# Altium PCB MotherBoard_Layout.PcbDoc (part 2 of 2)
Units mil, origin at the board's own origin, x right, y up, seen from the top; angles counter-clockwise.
Board outline 5200 x 4470 mil, 4 copper layers (Top Layer, Int1 (GND), Int2 (PWR), Bottom Layer), stack 53.912 mil thick; 91 components, 57 nets, 316 pads, 326 vias.
Unrouted connection lines stored in the file: 3.
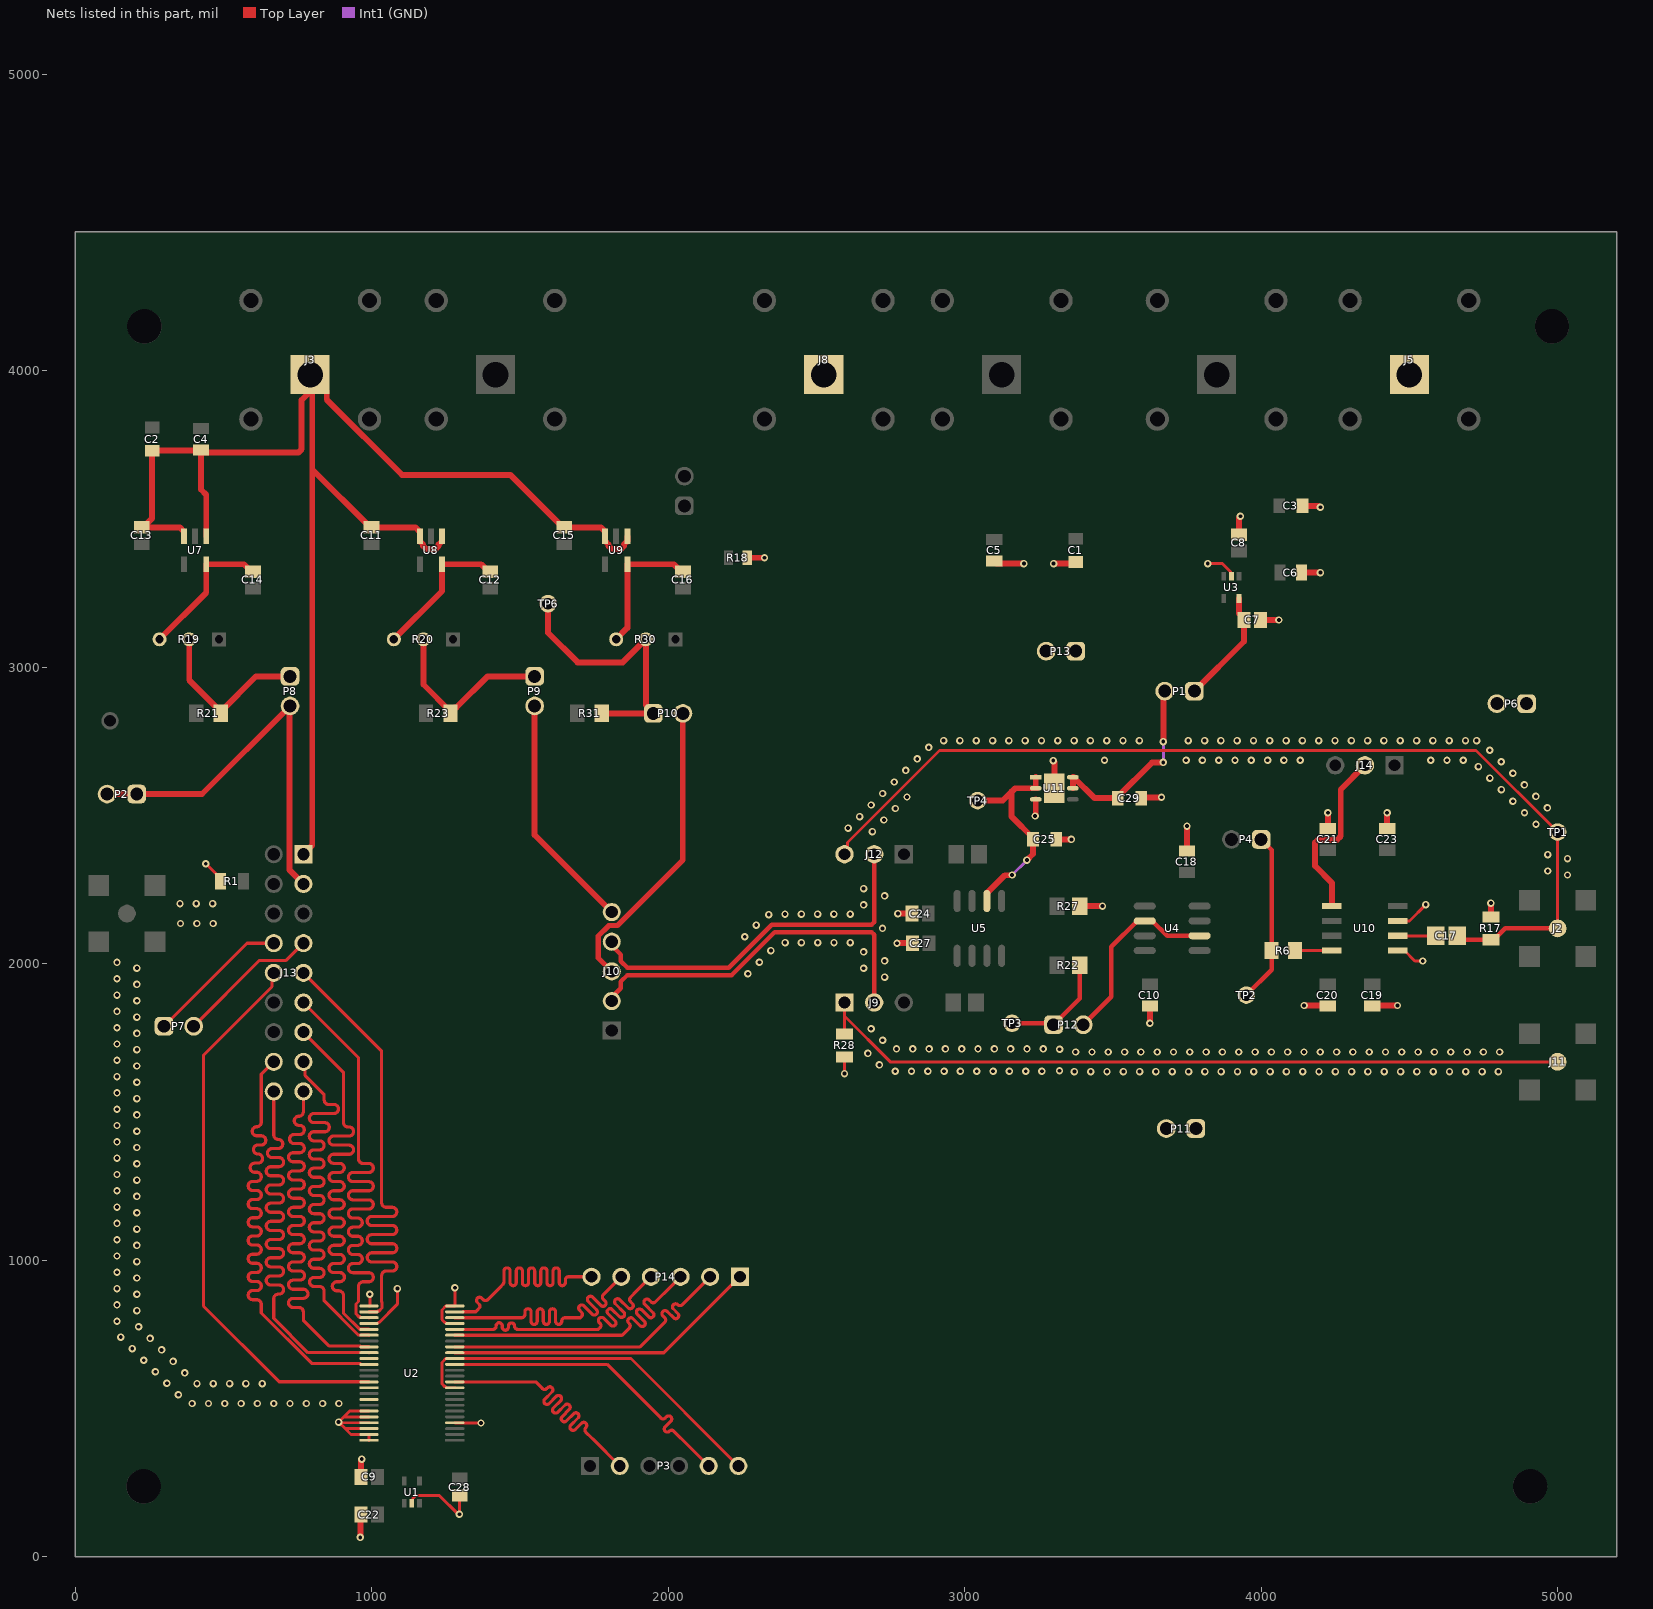
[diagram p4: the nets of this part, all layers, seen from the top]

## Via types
v1: diameter 25, hole 13, Top Layer to Bottom Layer, 326 vias

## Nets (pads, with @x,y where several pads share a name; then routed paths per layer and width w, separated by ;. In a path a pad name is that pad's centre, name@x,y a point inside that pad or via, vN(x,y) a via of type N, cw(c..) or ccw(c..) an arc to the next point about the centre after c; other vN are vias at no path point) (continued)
Code2: J13.16 U2.35 | length 1859.3
  Top Layer w10.7: J13.16@670,1670 628.14,1628.14 628.14,1526 628.14,1466.4 cw(c612.79,1466.4) 612.79,1451.05 ccw(c612.78,1435.7) 597.43,1435.7 ccw(c612.78,1435.7) 612.78,1420.34 628.14,1420.34 cw(c628.14,1404.99) 643.49,1404.99 cw(c628.14,1404.99) 628.14,1389.64 617.05,1389.64 ccw(c617.05,1374.29) 601.7,1374.29 ccw(c617.05,1374.29) 617.05,1358.94 cw(c617.05,1343.59) 632.4,1343.59 cw(c617.05,1343.59) 617.05,1328.24 605.89,1328.24 ccw(c605.89,1312.89) 590.54,1312.89 ccw(c605.89,1312.89) 605.89,1297.54 612.79,1297.53 cw(c612.79,1282.18) 628.14,1282.18 cw(c612.79,1282.18) 612.79,1266.83 599.05,1266.83 ccw(c599.05,1251.48) 583.7,1251.48 ccw(c599.05,1251.48) 599.05,1236.13 612.79,1236.13 cw(c612.79,1220.78) 628.14,1220.78 cw(c612.79,1220.78) 612.79,1205.43 599.05,1205.43 ccw(c599.05,1190.08) 583.7,1190.08 ccw(c599.05,1190.08) 599.05,1174.73 612.79,1174.73 cw(c612.79,1159.37) 628.14,1159.37 cw(c612.79,1159.37) 612.79,1144.02 599.05,1144.02 ccw(c599.05,1128.67) 583.7,1128.67 ccw(c599.05,1128.67) 599.05,1113.32 612.79,1113.32 cw(c612.79,1097.97) 628.14,1097.97 cw(c612.79,1097.97) 612.79,1082.62 599.05,1082.62 ccw(c599.05,1067.27) 583.7,1067.27 ccw(c599.05,1067.27) 599.05,1051.92 612.79,1051.92 cw(c612.79,1036.57) 628.14,1036.57 cw(c612.79,1036.57) 612.79,1021.21 599.05,1021.21 ccw(c599.05,1005.86) 583.7,1005.86 ccw(c599.05,1005.86) 599.05,990.51 612.79,990.51 cw(c612.79,975.16) 628.14,975.16 cw(c612.79,975.16) 612.79,959.81 599.05,959.81 ccw(c599.05,944.46) 583.7,944.46 ccw(c599.05,944.46) 599.05,929.11 612.79,929.11 cw(c612.79,913.76) 628.14,913.76 cw(c612.79,913.76) 612.79,898.41 599.05,898.41 ccw(c599.05,883.05) 583.7,883.05 ccw(c599.05,883.05) 599.05,867.7 612.79,867.7 cw(c612.79,852.35) 628.14,852.35 628.14,847 628.14,822.89 798.14,652.89 961.08,652.89 U2.35@964.06,649.91
Code2_BufferOut: P3.5 U2.14 | length 1067.4
  Top Layer w10.7: U2.14@1280.7,649.53 1794.47,649.53 1971.5,472.5 1975.28,468.72 ccw(c1982.85,476.28) 1990.42,468.72 1994.64,472.94 cw(c2001.96,465.62) 2009.28,472.94 cw(c2001.96,465.62) 2009.28,458.3 1989.92,438.94 ccw(c1997.24,431.62) 1989.92,424.3 ccw(c1997.24,431.62) 2004.56,424.3 cw(c2012.13,416.74) 2019.7,424.3 2043.22,400.78 2047,397 P3.5@2137,307
Code3: J13.18 U2.33 | length 1885.6
  Top Layer w10.7: J13.18@670,1570 670,1482 670,1423.7 ccw(c685.35,1423.7) 685.35,1408.34 cw(c685.35,1392.99) 700.7,1392.99 cw(c685.35,1392.99) 685.35,1377.64 664.46,1377.64 ccw(c664.46,1362.29) 649.11,1362.29 ccw(c664.46,1362.29) 664.46,1346.94 687.95,1346.94 cw(c687.95,1331.59) 703.3,1331.59 cw(c687.95,1331.59) 687.95,1316.24 660.19,1316.24 ccw(c660.19,1300.89) 644.84,1300.89 ccw(c660.19,1300.89) 660.19,1285.54 687.95,1285.53 cw(c687.95,1270.18) 703.3,1270.18 cw(c687.95,1270.18) 687.95,1254.83 660.19,1254.83 ccw(c660.19,1239.48) 644.84,1239.48 ccw(c660.19,1239.48) 660.19,1224.13 687.95,1224.13 cw(c687.95,1208.78) 703.3,1208.78 cw(c687.95,1208.78) 687.95,1193.43 660.19,1193.43 ccw(c660.19,1178.08) 644.84,1178.08 ccw(c660.19,1178.08) 660.19,1162.73 687.95,1162.73 cw(c687.95,1147.37) 703.3,1147.37 cw(c687.95,1147.37) 687.95,1132.02 660.19,1132.02 ccw(c660.19,1116.67) 644.84,1116.67 ccw(c660.19,1116.67) 660.19,1101.32 687.95,1101.32 cw(c687.95,1085.97) 703.3,1085.97 cw(c687.95,1085.97) 687.95,1070.62 660.19,1070.62 ccw(c660.19,1055.27) 644.84,1055.27 ccw(c660.19,1055.27) 660.19,1039.92 687.95,1039.92 cw(c687.95,1024.57) 703.3,1024.57 cw(c687.95,1024.57) 687.95,1009.21 660.19,1009.21 ccw(c660.19,993.86) 644.84,993.86 ccw(c660.19,993.86) 660.19,978.51 687.95,978.51 cw(c687.95,963.16) 703.3,963.16 cw(c687.95,963.16) 687.95,947.81 660.19,947.81 ccw(c660.19,932.46) 644.84,932.46 ccw(c660.19,932.46) 660.19,917.11 687.95,917.11 cw(c687.95,901.76) 703.3,901.76 cw(c687.95,901.76) 687.95,886.41 685.35,886.41 ccw(c685.35,871.05) 670,871.05 670,835 670,804.65 785.37,689.28 990.92,689.28 U2.33@991.3,688.9
Code3_BufferOut: P14.1 U2.16 | length 1067.4
  Top Layer w10.7: U2.16@1280.7,688.9 1985.9,688.9 P14.1@2242,945
Code4: J13.17 U2.32 | length 1886.7
  Top Layer w10.7: J13.17@770,1570 770,1501.69 cw(c754.65,1501.69) 754.65,1486.34 ccw(c754.65,1470.99) 739.3,1470.99 ccw(c754.65,1470.99) 754.65,1455.64 757.95,1455.64 cw(c757.95,1440.29) 773.3,1440.29 cw(c757.95,1440.29) 757.95,1424.94 738.86,1424.94 ccw(c738.86,1409.59) 723.51,1409.59 ccw(c738.86,1409.59) 738.86,1394.24 757.95,1394.24 cw(c757.95,1378.89) 773.3,1378.89 cw(c757.95,1378.88) 757.95,1363.53 735.35,1363.53 ccw(c735.35,1348.18) 720,1348.18 ccw(c735.35,1348.18) 735.35,1332.83 757.95,1332.83 cw(c757.95,1317.48) 773.3,1317.48 cw(c757.95,1317.48) 757.95,1302.13 735.35,1302.13 ccw(c735.35,1286.78) 720,1286.78 ccw(c735.35,1286.78) 735.35,1271.43 757.95,1271.43 cw(c757.95,1256.08) 773.3,1256.08 cw(c757.95,1256.08) 757.95,1240.72 735.35,1240.72 ccw(c735.35,1225.37) 720,1225.37 ccw(c735.35,1225.37) 735.35,1210.02 757.95,1210.02 cw(c757.95,1194.67) 773.3,1194.67 cw(c757.95,1194.67) 757.95,1179.32 735.35,1179.32 ccw(c735.35,1163.97) 720,1163.97 ccw(c735.35,1163.97) 735.35,1148.62 757.95,1148.62 cw(c757.95,1133.27) 773.3,1133.27 cw(c757.95,1133.27) 757.95,1117.92 735.35,1117.92 ccw(c735.35,1102.56) 720,1102.56 ccw(c735.35,1102.56) 735.35,1087.21 757.95,1087.21 cw(c757.95,1071.86) 773.3,1071.86 cw(c757.95,1071.86) 757.95,1056.51 735.35,1056.51 ccw(c735.35,1041.16) 720,1041.16 ccw(c735.35,1041.16) 735.35,1025.81 757.95,1025.81 cw(c757.95,1010.46) 773.3,1010.46 cw(c757.95,1010.46) 757.95,995.11 735.35,995.11 ccw(c735.35,979.76) 720,979.76 ccw(c735.35,979.76) 735.35,964.4 758.77,964.4 cw(c758.77,949.05) 774.12,949.05 cw(c758.77,949.05) 758.77,933.7 735.35,933.7 ccw(c735.35,918.35) 720,918.35 ccw(c735.35,918.35) 735.35,903 770.07,903 cw(c770.07,887.65) 785.42,887.65 cw(c770.07,887.65) 770.07,872.3 735.35,872.3 ccw(c735.35,856.95) 720,856.95 ccw(c735.35,856.95) 735.35,841.59 754.65,841.59 cw(c754.65,826.24) 770,826.24 770,820.89 770,798 856.05,711.95 961.08,711.95 964.06,708.96 990.92,708.96 U2.32@991.3,708.58
Code4_BufferOut: P14.2 U2.17 | length 1067.4
  Top Layer w10.7: U2.17@1280.7,708.58 1905.58,708.58 1985,788 1988.78,791.78 ccw(c1981.22,799.35) 1988.78,806.92 1982.46,813.25 cw(c1989.78,820.57) 1982.46,827.88 cw(c1989.78,820.57) 1997.1,827.88 2018.48,806.5 ccw(c2025.8,813.82) 2033.12,806.5 ccw(c2025.8,813.82) 2033.12,821.14 2018.06,836.2 cw(c2025.38,843.52) 2018.06,850.84 cw(c2025.38,843.52) 2032.7,850.84 ccw(c2040.27,858.4) 2047.84,850.84 2109,912 P14.2@2142,945
Code5: J13.15 U2.30 | length 1887.4
  Top Layer w10.7: J13.15@770,1670 775.77,1664.23 775.77,1623.43 840,1559.2 840,1546.97 840,1541.62 ccw(c855.35,1541.62) 855.35,1526.27 872.95,1526.27 cw(c872.95,1510.92) 888.3,1510.92 cw(c872.95,1510.92) 872.95,1495.57 805.35,1495.57 ccw(c805.35,1480.22) 790,1480.22 ccw(c805.35,1480.22) 805.35,1464.87 842.17,1464.87 cw(c842.17,1449.51) 857.52,1449.51 cw(c842.17,1449.51) 842.17,1434.16 805.35,1434.16 ccw(c805.35,1418.81) 790,1418.81 ccw(c805.35,1418.81) 805.35,1403.46 824.65,1403.46 cw(c824.65,1388.11) 840,1388.11 cw(c824.65,1388.11) 824.65,1372.76 805.35,1372.76 ccw(c805.35,1357.41) 790,1357.41 ccw(c805.35,1357.41) 805.35,1342.06 824.65,1342.06 cw(c824.65,1326.7) 840,1326.7 cw(c824.65,1326.7) 824.65,1311.35 805.35,1311.35 ccw(c805.35,1296) 790,1296 ccw(c805.35,1296) 805.35,1280.65 824.65,1280.65 cw(c824.65,1265.3) 840,1265.3 cw(c824.65,1265.3) 824.65,1249.95 805.35,1249.95 ccw(c805.35,1234.6) 790,1234.6 ccw(c805.35,1234.6) 805.35,1219.25 824.65,1219.25 cw(c824.65,1203.9) 840,1203.9 cw(c824.65,1203.9) 824.65,1188.54 805.35,1188.54 ccw(c805.35,1173.19) 790,1173.19 ccw(c805.35,1173.19) 805.35,1157.84 824.65,1157.84 cw(c824.65,1142.49) 840,1142.49 cw(c824.65,1142.49) 824.65,1127.14 805.35,1127.14 ccw(c805.35,1111.79) 790,1111.79 ccw(c805.35,1111.79) 805.35,1096.44 824.65,1096.44 cw(c824.65,1081.09) 840,1081.09 cw(c824.65,1081.09) 824.65,1065.74 805.35,1065.74 ccw(c805.35,1050.38) 790,1050.38 ccw(c805.35,1050.38) 805.35,1035.03 824.65,1035.03 cw(c824.65,1019.68) 840,1019.68 cw(c824.65,1019.68) 824.65,1004.33 805.35,1004.33 ccw(c805.35,988.98) 790,988.98 ccw(c805.35,988.98) 805.35,973.63 824.65,973.63 cw(c824.65,958.28) 840,958.28 cw(c824.65,958.28) 824.65,942.93 806.18,942.93 ccw(c806.18,927.57) 790.83,927.57 ccw(c806.18,927.57) 806.18,912.22 824.65,912.22 cw(c824.65,896.87) 840,896.87 840,864.3 955.97,748.33 990.92,748.33 U2.30@991.3,747.95
Code5_BufferOut: P14.3 U2.19 | length 1065.3
  Top Layer w10.7: U2.19@1280.7,747.95 1844.95,747.95 1865.28,768.28 1869.07,772.07 ccw(c1861.5,779.64) 1869.07,787.2 1866.98,789.29 cw(c1874.3,796.61) 1866.98,803.93 cw(c1874.3,796.61) 1881.62,803.93 1905.17,780.38 ccw(c1912.49,787.7) 1919.81,780.38 ccw(c1912.49,787.7) 1919.81,795.02 1896.26,818.57 cw(c1903.58,825.89) 1896.26,833.21 cw(c1903.58,825.89) 1910.9,833.21 1934.45,809.66 ccw(c1941.77,816.98) 1949.08,809.66 ccw(c1941.77,816.98) 1949.08,824.3 1921.3,852.09 cw(c1928.62,859.4) 1921.3,866.72 cw(c1928.62,859.4) 1935.94,866.72 1942.26,860.4 ccw(c1949.83,867.97) 1957.4,860.4 2010,913 P14.3@2042,945
Code6: J13.13 U2.29 | length 1886
  Top Layer w10.7: J13.13@770,1770 905,1635 905,1471 905,1465.65 ccw(c920.35,1465.65) 920.35,1450.3 923.92,1450.3 cw(c923.92,1434.95) 939.27,1434.95 cw(c923.92,1434.95) 923.92,1419.59 872.05,1419.59 ccw(c872.05,1404.24) 856.7,1404.24 ccw(c872.05,1404.24) 872.05,1388.89 923.92,1388.89 cw(c923.92,1373.54) 939.27,1373.54 cw(c923.92,1373.54) 923.92,1358.19 872.05,1358.19 ccw(c872.05,1342.84) 856.7,1342.84 ccw(c872.05,1342.84) 872.05,1327.49 892.4,1327.49 cw(c892.4,1312.14) 907.75,1312.14 cw(c892.4,1312.14) 892.4,1296.79 872.05,1296.79 ccw(c872.05,1281.43) 856.7,1281.43 ccw(c872.05,1281.43) 872.05,1266.08 892.4,1266.08 cw(c892.4,1250.73) 907.75,1250.73 cw(c892.4,1250.73) 892.4,1235.38 872.05,1235.38 ccw(c872.05,1220.03) 856.7,1220.03 ccw(c872.05,1220.03) 872.05,1204.68 892.4,1204.68 cw(c892.4,1189.33) 907.75,1189.33 cw(c892.4,1189.33) 892.4,1173.98 872.05,1173.98 ccw(c872.05,1158.63) 856.7,1158.63 ccw(c872.05,1158.63) 872.05,1143.27 892.4,1143.27 cw(c892.4,1127.92) 907.75,1127.92 cw(c892.4,1127.92) 892.4,1112.57 872.05,1112.57 ccw(c872.05,1097.22) 856.7,1097.22 ccw(c872.05,1097.22) 872.05,1081.87 892.4,1081.87 cw(c892.4,1066.52) 907.75,1066.52 cw(c892.4,1066.52) 892.4,1051.17 872.05,1051.17 ccw(c872.05,1035.82) 856.7,1035.82 ccw(c872.05,1035.82) 872.05,1020.47 892.4,1020.47 cw(c892.4,1005.11) 907.75,1005.11 cw(c892.4,1005.11) 892.4,989.76 872.05,989.76 ccw(c872.05,974.41) 856.7,974.41 ccw(c872.05,974.41) 872.05,959.06 892.97,959.06 cw(c892.97,943.71) 908.32,943.71 cw(c892.97,943.71) 892.97,928.36 883.01,928.36 ccw(c883.01,913.01) 867.65,913.01 ccw(c883.01,913.01) 883.01,897.66 889.65,897.66 cw(c889.65,882.3) 905,882.3 905,840 905,822.92 959.91,768.02 990.92,768.02 U2.29@991.3,767.64
Code6_BufferOut: P14.4 U2.20 | length 1067.4
  Top Layer w10.7: U2.20@1280.7,767.64 1404,767.64 1409.35,767.64 ccw(c1409.35,778.34) 1420.05,778.34 1420.05,779.95 cw(c1430.41,779.95) 1430.41,790.31 cw(c1430.41,779.95) 1440.76,779.95 1440.76,775.01 ccw(c1451.11,775.01) 1451.11,764.66 ccw(c1451.11,775.01) 1461.46,775.01 1461.46,779.1 cw(c1471.81,779.1) 1471.81,789.45 cw(c1471.81,779.1) 1482.16,779.1 1482.16,778.34 ccw(c1492.86,778.34) 1492.86,767.64 1751,767.64 1764.64,767.64 1766.53,769.53 1770.31,773.31 ccw(c1762.75,780.88) 1770.31,788.45 1768.22,790.54 cw(c1775.54,797.86) 1768.22,805.18 cw(c1775.54,797.86) 1782.86,805.18 1806.41,781.63 ccw(c1813.73,788.95) 1821.05,781.63 ccw(c1813.73,788.95) 1821.05,796.27 1797.5,819.82 cw(c1804.82,827.14) 1797.5,834.45 cw(c1804.82,827.14) 1812.14,834.46 1835.69,810.9 ccw(c1843.01,818.22) 1850.33,810.9 ccw(c1843.01,818.22) 1850.33,825.54 1822.54,853.33 cw(c1829.86,860.65) 1822.54,867.97 cw(c1829.86,860.65) 1837.18,867.97 1864.97,840.18 ccw(c1872.29,847.5) 1879.61,840.18 ccw(c1872.29,847.5) 1879.61,854.82 1873.28,861.15 cw(c1880.85,868.71) 1873.28,876.28 1893,896 P14.4@1942,945
Code7: J13.11 U2.27 | length 1882.1
  Top Layer w10.7: J13.11@770,1870 955.97,1684.03 955.97,1348 955.97,1342.65 ccw(c971.32,1342.65) 971.32,1327.3 990.62,1327.3 cw(c990.62,1311.95) 1005.97,1311.95 cw(c990.62,1311.95) 990.62,1296.59 937.05,1296.59 ccw(c937.05,1281.24) 921.7,1281.24 ccw(c937.05,1281.24) 937.05,1265.89 990.62,1265.89 cw(c990.62,1250.54) 1005.97,1250.54 cw(c990.62,1250.54) 990.62,1235.19 937.05,1235.19 ccw(c937.05,1219.84) 921.7,1219.84 ccw(c937.05,1219.84) 937.05,1204.49 990.62,1204.49 cw(c990.62,1189.14) 1005.97,1189.14 cw(c990.62,1189.14) 990.62,1173.79 937.05,1173.79 ccw(c937.05,1158.43) 921.7,1158.43 ccw(c937.05,1158.43) 937.05,1143.08 953.18,1143.08 cw(c953.18,1127.73) 968.54,1127.73 cw(c953.18,1127.73) 953.18,1112.38 937.05,1112.38 ccw(c937.05,1097.03) 921.7,1097.03 ccw(c937.05,1097.03) 937.05,1081.68 953.18,1081.68 cw(c953.18,1066.33) 968.54,1066.33 cw(c953.18,1066.33) 953.18,1050.98 937.05,1050.98 ccw(c937.05,1035.63) 921.7,1035.63 ccw(c937.05,1035.63) 937.05,1020.27 953.18,1020.27 cw(c953.18,1004.92) 968.54,1004.92 cw(c953.18,1004.92) 953.18,989.57 937.05,989.57 ccw(c937.05,974.22) 921.7,974.22 ccw(c937.05,974.22) 937.05,958.87 990.62,958.87 cw(c990.62,943.52) 1005.97,943.52 cw(c990.62,943.52) 990.62,928.17 971.32,928.17 ccw(c971.32,912.82) 955.97,912.82 955.97,861.75 947.36,853.14 947.36,819.93 956.92,810.37 961.08,810.37 964.06,807.39 990.92,807.39 U2.27@991.3,807.01
Code7_BufferOut: P14.5 U2.22 | length 1067.2
  Top Layer w10.7: U2.22@1280.7,807.01 1501,807.01 1506.35,807.01 ccw(c1506.35,817.71) 1517.05,817.71 1517.05,826.66 cw(c1527.41,826.66) 1527.41,837.01 cw(c1527.41,826.66) 1537.76,826.66 1537.76,794.69 ccw(c1548.11,794.69) 1548.11,784.34 ccw(c1548.11,794.69) 1558.46,794.69 1558.46,826.66 cw(c1568.81,826.66) 1568.81,837.01 cw(c1568.81,826.66) 1579.16,826.66 1579.16,794.69 ccw(c1589.51,794.69) 1589.51,784.34 ccw(c1589.51,794.69) 1599.86,794.69 1599.86,826.66 cw(c1610.21,826.66) 1610.21,837.01 cw(c1610.21,826.66) 1620.57,826.66 1620.57,794.69 ccw(c1630.92,794.69) 1630.92,784.34 ccw(c1630.92,794.69) 1641.27,794.69 1641.27,796.31 cw(c1651.97,796.31) 1651.97,807.01 1688,807.01 1704.01,807.01 1707.79,810.79 ccw(c1700.22,818.36) 1707.79,825.93 1701.47,832.25 cw(c1708.79,839.57) 1701.47,846.89 cw(c1708.79,839.57) 1716.1,846.89 1743.89,819.1 ccw(c1751.21,826.42) 1758.53,819.1 ccw(c1751.21,826.42) 1758.53,833.74 1730.74,861.53 cw(c1738.06,868.85) 1730.74,876.17 cw(c1738.06,868.85) 1745.38,876.17 1773.17,848.38 ccw(c1780.49,855.7) 1787.81,848.38 ccw(c1780.49,855.7) 1787.81,863.02 1781.48,869.35 cw(c1789.05,876.91) 1781.48,884.48 1804.5,907.5 P14.5@1842,945
Code8: J13.9 U2.26 | length 1886.6
  Top Layer w10.7: J13.9@770,1970 1034,1706 1034,1200 1034,1194.65 ccw(c1049.35,1194.65) 1049.35,1179.3 1069.89,1179.3 cw(c1069.89,1163.95) 1085.24,1163.95 cw(c1069.89,1163.95) 1069.89,1148.59 1000.59,1148.59 ccw(c1000.59,1133.24) 985.24,1133.24 ccw(c1000.59,1133.24) 1000.59,1117.89 1069.89,1117.89 cw(c1069.89,1102.54) 1085.24,1102.54 cw(c1069.89,1102.54) 1069.89,1087.19 1000.59,1087.19 ccw(c1000.59,1071.84) 985.24,1071.84 ccw(c1000.59,1071.84) 1000.59,1056.49 1069.89,1056.49 cw(c1069.89,1041.14) 1085.24,1041.14 cw(c1069.89,1041.14) 1069.89,1025.79 1000.59,1025.79 ccw(c1000.59,1010.43) 985.24,1010.43 ccw(c1000.59,1010.43) 1000.59,995.08 1069.89,995.08 cw(c1069.89,979.73) 1085.24,979.73 cw(c1069.89,979.73) 1069.89,964.38 1049.35,964.38 ccw(c1049.35,949.03) 1034,949.03 1034,860.53 1034.62,859.91 1035.24,859.29 1035.24,839.62 1025.68,830.06 1021.52,830.06 1018.54,827.07 991.68,827.07 U2.26@991.3,826.69
Code8_BufferOut: P14.6 U2.23 | length 1040.1
  Top Layer w10.7: U2.23@1307.94,827.07 1351.07,827.07 1358.36,834.36 1362.15,838.15 ccw(c1354.58,845.71) 1362.15,853.28 1357.11,858.32 cw(c1364.43,865.64) 1357.11,872.95 cw(c1364.43,865.64) 1371.75,872.95 1376.78,867.92 ccw(c1384.35,875.49) 1391.92,867.92 1435.49,911.49 1436,912 1441.35,917.35 ccw(c1428.86,929.85) 1446.53,929.85 1446.53,964.65 cw(c1456.88,964.65) 1456.88,975 cw(c1456.88,964.65) 1467.23,964.65 1467.23,925.35 ccw(c1477.58,925.35) 1477.58,915 ccw(c1477.58,925.35) 1487.93,925.35 1487.93,964.65 cw(c1498.28,964.65) 1498.28,975 cw(c1498.28,964.65) 1508.63,964.65 1508.63,925.35 ccw(c1518.99,925.35) 1518.99,915 ccw(c1518.99,925.35) 1529.34,925.35 1529.34,964.65 cw(c1539.69,964.65) 1539.69,975 cw(c1539.69,964.65) 1550.04,964.65 1550.04,925.35 ccw(c1560.39,925.35) 1560.39,915 ccw(c1560.39,925.35) 1570.74,925.35 1570.74,964.65 cw(c1581.09,964.65) 1581.09,975 cw(c1581.09,964.65) 1591.44,964.65 1591.44,925.35 ccw(c1601.79,925.35) 1601.79,915 ccw(c1601.79,925.35) 1612.15,925.35 1612.15,964.65 cw(c1622.5,964.65) 1622.5,975 cw(c1622.5,964.65) 1632.85,964.65 1632.85,925.35 ccw(c1643.2,925.35) 1643.2,915 ccw(c1643.2,925.35) 1653.55,925.35 1653.55,934.3 cw(c1664.25,934.3) 1664.25,945 1682,945 P14.6@1742,945
DGND: C1.2 C3.2 C5.2 C6.2 C7.1 C8.1 C9.1 C10.2 C18.2 C19.2 C20.2 C21.2 C22.1 C23.2 C24.1 C25.2 C27.1 C28.1 C29.2 J5.1 J8.1 P3.6 P6.1 P6.2 P11.1 P11.2 P13.1 P13.2 R1.2 R17.2 R18.2 R27.1 R28.1 U1.2 U2.4 U2.10 U2.15 U2.21 U2.24 U2.25 U2.28 U2.34 U2.39 U2.41 U2.43 U2.44 U2.45 U2.46 U2.47 U2.48 U3.2 U10.1 U10.3 U11.3 U11.7 | length 4612.3
  Top Layer w10: v1(441,2338) 441.46,2338 490.61,2288.84 R1.2@490.61,2279 ; 910.42,472.36 U2.44@991.3,472.36 ; U2.45@991.3,452.68 v1@891.29,452.71 ; U2.48@991.3,393.62 U2.47@991.3,413.31 930.69,413.31 911.01,432.99 ; U2.46@991.3,432.99 911.01,432.99 ; U2.43@991.3,492.05 926.05,492.05 v1(889,455) v1@891.29,452.71 ; U2.28@991.3,787.32 1018.86,787.32 1022.57,791.04 1025.53,791.04 1087,852.51 v1(1087,905) ; U2.25@991.3,846.38 U2.25@993.97,846.38 ; U2.25@994,846.41 v1(994,886) ; U1.2@1136,181.6 1138.87,184.47 1138.87,197.08 1149.16,207.36 1228.64,207.36 1292,144 v1(1296,144) 1296,207.44 C28.1@1297,208.44 ; U2.15@1280.7,669.21 1250.15,669.18 1237.11,656.14 1237.11,583.86 1246.47,574.5 1249.43,574.5 1253.14,570.79 U2.10@1280.7,570.79 ; U2.24@1280.67,846.35 1250.15,846.35 1237.11,833.31 1237.11,800.39 1246.47,791.04 1249.43,791.04 1253.14,787.32 U2.21@1280.7,787.32 ; U2.15@1280.7,669.21 1874.79,669.21 P3.6@2237,307 ; U2.24@1280.7,846.38 U2.24@1280.97,846.38 ; U2.4@1280.73,452.65 1368.35,452.65 v1(1369,452) ; U2.24@1281,846.41 v1(1281,908) ; v1(2595,1630) R28.1@2595,1686.61 ; v1(3820,3350) 3870.01,3350 3897.13,3322.88 3897.13,3310.28 U3.2@3900,3307.4 ; C20.2@4223.58,1860 C20.2@4225,1858.58 ; C19.2@4375,1858.58 C19.2@4376.42,1860 ; U10.1@4461.25,2045 4483.5,2045 4518.5,2010 v1(4545,2010) ; U10.3@4461.25,2145 4500,2145 v1(4555,2200) ; v1@891.29,452.71 911.01,432.99
  Top Layer w20: v1(962,66) 962.96,66.96 962.96,141.52 C22.1@964.44,143 ; C9.1@964.44,270 964.44,326.09 967,328.65 v1(967,330) ; R18.2@2266.5,3370 v1(2325,3370) ; v1(2772,2070) C27.1@2824.44,2070 ; v1(2775,2170) C24.1@2822.44,2170 ; C5.2@3100,3358.58 3107.63,3350.96 3199.04,3350.96 v1(3200,3350) ; v1(3238,2499) 3238,2500.35 3240,2502.35 U11.3@3240,2555.2 ; U11.7@3278.42,2555.2 3302.86,2579.65 U11.7@3302.86,2592.6 3302.86,2680.78 3299,2684.65 v1(3299,2686) ; v1(3300,3350) 3369.37,3350 C1.2@3375,3355.63 ; C25.2@3306.42,2420 v1(3360,2420) ; R27.1@3388.43,2195 v1(3465,2195) ; C29.2@3595.37,2559 3597.41,2561.04 3663.04,2561.04 v1(3664,2562) ; v1(3625,1800) C10.2@3625,1858.58 ; C18.2@3750,2381.42 v1(3750,2465) ; C8.1@3925,3447.56 3925,3503.65 3930,3508.65 v1(3930,3510) ; C7.1@3997.56,3160 v1(4060,3160) ; C6.2@4136.42,3320 v1(4200,3320) ; C3.2@4139.37,3545 4193.65,3545 4198.65,3540 v1(4200,3540) ; v1(4145,1860) C20.2@4223.58,1860 ; C21.2@4225,2456.42 v1(4225,2510) ; C19.2@4376.42,1860 v1(4460,1860) ; C23.2@4425,2456.42 v1(4425,2510) ; R17.2@4775,2158.39 v1(4775,2205)
  other v1: 394.95,517.57 449.95,517.57 504.95,517.57 559.95,517.57 614.95,517.57 669.95,517.57 724.95,517.57 779.95,517.57 834.95,517.57 889.95,517.57 348.52,547.06 411.27,584.63 466.27,584.63 521.27,584.63 576.27,584.63 631.27,584.63 309.63,585.95 369.73,620.68 270.74,624.84 330.84,659.57 231.85,663.74 291.95,698.46 192.96,702.63 253.06,737.36 154.07,741.52 214.17,776.25 141.47,795.06 208.53,830.96 141.47,850.06 208.53,885.96 141.47,905.06 208.53,940.96 141.47,960.06 208.53,995.96 141.47,1015.06 208.53,1050.96 141.47,1070.06 208.53,1105.96 141.47,1125.06 208.53,1160.96 141.47,1180.06 208.53,1215.96 141.47,1235.06 208.53,1270.96 141.47,1290.06 208.53,1325.96 141.47,1345.06 208.53,1380.96 141.47,1400.06 208.53,1435.96 141.47,1455.06 208.53,1490.96 141.47,1510.06 208.53,1545.96 141.47,1565.06 208.53,1600.96 141.47,1620.06 3370.29,1636.85 3425.29,1636.85 3480.29,1636.85 3535.29,1636.85 3590.29,1636.85 3645.29,1636.85 3700.29,1636.85 3755.29,1636.85 3810.29,1636.85 3865.29,1636.85 3920.29,1636.85 3975.29,1636.85 4030.29,1636.85 4085.29,1636.85 4140.29,1636.85 4195.29,1636.85 4250.29,1636.85 4305.29,1636.85 4360.29,1636.85 4415.29,1636.85 4470.29,1636.85 4525.29,1636.85 4580.29,1636.85 4635.29,1636.85 4690.29,1636.85 4745.29,1636.85 4800.29,1636.85 2766,1638 2821,1638 2876,1638 2931,1638 2986,1638 3041,1638 3096,1638 3151,1638 3206,1638 3260.85,1638 3320,1640 208.53,1655.96 2712.53,1659.68 141.47,1675.06 2673.64,1698.57 3374.51,1703.15 3429.51,1703.15 3484.51,1703.15 3539.51,1703.15 3594.51,1703.15 3649.51,1703.15 3704.51,1703.15 3759.51,1703.15 3814.51,1703.15 3869.51,1703.15 3924.51,1703.15 3979.51,1703.15 4034.51,1703.15 4089.51,1703.15 4144.51,1703.15 4199.51,1703.15 4254.51,1703.15 4309.51,1703.15 4364.51,1703.15 4419.51,1703.15 4474.51,1703.15 4529.51,1703.15 4584.51,1703.15 4639.51,1703.15 4694.51,1703.15 4749.51,1703.15 4804.51,1703.15 208.53,1710.96 3320.26,1712.2 2770.28,1713.68 2825.28,1713.68 2880.28,1713.68 2935.28,1713.68 2990.28,1713.68 3045.28,1713.68 3100.28,1713.68 3155.28,1713.68 3210.28,1713.68 3265.28,1713.68 141.47,1730.06 2723.45,1742.52 208.53,1765.96 2684.56,1781.41 141.47,1785.06 208.53,1820.96 141.47,1840.06 208.53,1875.96 141.47,1895.06 208.53,1930.96 141.47,1950.06 2730.38,1955.55 2269.06,1967.01 208.53,1985.96 2659.62,1985.55 141.47,2005.06 2307.95,2005.9 2730.38,2010.55 2659.62,2040.55 2346.84,2044.79 2394.57,2072.12 2449.57,2072.12 2504.57,2072.12 2559.57,2072.12 2614.57,2072.12 2258.5,2091.89 2723.12,2120.07 2297.4,2130.79 355.73,2136.47 410.73,2136.47 465.73,2136.47 2339.4,2166.29 2394.38,2167.88 2449.38,2167.88 2504.38,2167.88 2559.38,2167.88 2614.38,2167.88 2659.62,2199.17 353.8,2203.53 408.8,2203.53 463.8,2203.53 2730.38,2229.58 2659.62,2254.17 5033.15,2300.13 4966.85,2313.63 5033.15,2355.13 4966.85,2368.63 2689.01,2446.51 2606.96,2458.23 4927,2471.12 2727.9,2485.4 2645.85,2497.12 4888.11,2510.01 2766.79,2524.29 4965.61,2526.27 2684.75,2536.01 4849.22,2548.9 2805.68,2563.18 4926.72,2565.16 2723.64,2574.9 4810.33,2587.79 4887.83,2604.05 2762.53,2613.79 4771.44,2626.68 4848.94,2642.94 2801.42,2652.68 4732.55,2665.57 4810.05,2681.83 3471.89,2686.99 3746.89,2686.99 3801.89,2686.99 3856.89,2686.99 3911.89,2686.99 3966.89,2686.99 4021.89,2686.99 4076.89,2686.99 4131.89,2686.99 4571.89,2686.99 4626.89,2686.99 4681.89,2686.99 2840.31,2691.57 4771.16,2720.72 2879.2,2730.46 2929.24,2753.29 2984.24,2753.29 3039.24,2753.29 3094.24,2753.29 3149.24,2753.29 3204.24,2753.29 3259.24,2753.29 3314.24,2753.29 3369.24,2753.29 3424.24,2753.29 3479.24,2753.29 3534.24,2753.29 3589.24,2753.29 3754.24,2753.29 3809.24,2753.29 3864.24,2753.29 3919.24,2753.29 3974.24,2753.29 4029.24,2753.29 4084.24,2753.29 4139.24,2753.29 4194.24,2753.29 4249.24,2753.29 4304.24,2753.29 4359.24,2753.29 4414.24,2753.29 4469.24,2753.29 4524.24,2753.29 4579.24,2753.29 4634.24,2753.29 4689.24,2753.29 4726.66,2753.05
EOC: J13.10 U2.38 | length 1886.3
  Top Layer w10.7: J13.10@670,1970 664.23,1964.23 664.23,1923.43 433,1692.2 433,846 688.15,590.85 990.92,590.85 U2.38@991.3,590.47
EOC_BufferOut: P3.2 U2.11 | length 1067.4
  Top Layer w10.7: U2.11@1280.7,590.47 1553.53,590.47 1572,572 1575.78,568.22 ccw(c1583.35,575.78) 1590.92,568.22 1593.82,571.12 cw(c1601.14,563.8) 1608.46,571.12 cw(c1601.14,563.8) 1608.46,556.48 1584.1,532.12 ccw(c1591.42,524.8) 1584.1,517.48 ccw(c1591.42,524.8) 1598.74,517.48 1623.1,541.84 cw(c1630.42,534.52) 1637.74,541.84 cw(c1630.42,534.52) 1637.74,527.2 1613.37,502.84 ccw(c1620.69,495.52) 1613.37,488.2 ccw(c1620.69,495.52) 1628.01,488.2 1652.38,512.57 cw(c1659.7,505.25) 1667.02,512.57 cw(c1659.7,505.25) 1667.02,497.93 1642.65,473.56 ccw(c1649.97,466.24) 1642.65,458.92 ccw(c1649.97,466.24) 1657.29,458.92 1681.66,483.29 cw(c1688.98,475.97) 1696.29,483.29 cw(c1688.98,475.97) 1696.29,468.65 1672.13,444.49 ccw(c1679.45,437.17) 1672.13,429.85 ccw(c1679.45,437.17) 1686.77,429.85 1708.03,451.11 cw(c1715.35,443.79) 1722.67,451.11 cw(c1715.35,443.79) 1722.67,436.47 ccw(c1730.24,428.9) 1722.67,421.33 1741.72,402.28 1745.5,398.5 P3.2@1837,307
For_AVDD_ESD_1.5V: C12.2 R20.3 U8.5 | length 493.4
  Top Layer w20: R20.3@1075,3095 1237.4,3257.4 U8.5@1237.4,3348 1369.64,3348 1395.08,3322.56 C12.2@1400,3322.56
For_AVDD_ESD_1V: J10.5 P9.2 | length 802.7
  Top Layer w20: P9.2@1550,2870 1550,2435 J10.5@1810,2175
For_DVDD_1.5V: C14.2 R19.3 U7.5 | length 486.3
  Top Layer w20: R19.3@285,3095 442.4,3252.4 U7.5@442.4,3348 569.64,3348 595.08,3322.56 C14.2@600,3322.56
For_DVDD_1V: J13.3 P2.1 P2.2 P8.2 | length 1357.8
  Top Layer w20: P2.2@108,2573 P2.1@208,2573 428,2573 P8.2@723.49,2868.49 ; P8.2@725,2870 P8.2@723.49,2868.49 ; J13.3@770,2270 723.49,2316.51 P8.2@723.49,2868.49
For_VCM_0.5V: J10.3 P10.2 | length 1023.9
  Top Layer w18: J10.3@1810,1975 1764.49,2020.51 1764.49,2093.85 1800.12,2129.49 1828.85,2129.49 2050,2350.64 P10.2@2050,2845
For_VCM_1.5V: C16.2 R30.3 U9.5 | length 466.6
  Top Layer w20: R30.3@1825,3095 1825,3096.03 1862.4,3133.43 U9.5@1862.4,3348 2019.64,3348 2045.08,3322.56 C16.2@2050,3322.56
IN_T12_N: J9.2 J10.2 | length 1234
  Top Layer w15: J10.2@1810,1875 1810,1887.45 1840.8,1918.26 1840.8,1940.5 1862.8,1962.5 2214.51,1962.5 2359.51,2107.5 2686.21,2107.5 2695,2098.71 J9.2@2695,1870
IN_T12_P: J10.4 J12.2 | length 1234
  Top Layer w15: J10.4@1810,2075 1810,2062.55 1840.8,2031.74 1840.8,2009.5 1862.8,1987.5 2204.15,1987.5 2349.15,2132.5 2686.21,2132.5 2695,2141.29 J12.2@2695,2370
LDO_OUT_2.5V: C29.1 P1.2 U11.5 U11.6 | length 666.9
  Top Layer w20: U11.5@3365,2592.6 U11.6@3365,2630 3367.38,2630 3438.38,2559 C29.1@3516.63,2559 3516.63,2563.92 3631.75,2679.04 3669.04,2679.04 v1(3670,2680) ; v1(3670,2750) 3670.96,2750.96 3670.96,2915.96 P1.2@3675,2920
  Int1 (GND) w10: v1(3670,2680) v1(3670,2750)
MUX0: J13.8 P7.1 | length 486
  Top Layer w10.7: P7.1@300,1790 580,2070 J13.8@670,2070
MUX1: J13.7 P7.2 | length 486
  Top Layer w10.7: P7.2@400,1790 621.86,2011.86 711.86,2011.86 J13.7@770,2070
NetC7_2: C7.2 P1.1 U3.5 | length 388.9
  Top Layer w20: P1.1@3775,2920 3942.44,3087.44 C7.2@3942.44,3160 3942.44,3164.92 3925.59,3181.77 U3.5@3925.59,3232.6
NetC17_2: C17.2 U10.2 | length 127.3
  Top Layer w10: U10.2@4461.25,2095 C17.2@4588.58,2095
NetJ14_2: J14.2 U10.5 | length 606.6
  Top Layer w20: U10.5@4238.75,2195 4238.75,2273.55 4181.44,2330.86 4181.44,2408.91 4190.81,2418.28 4255.75,2418.28 4268.56,2431.09 4268.56,2588.56 J14.2@4350,2670
NetP4_1: P4.1 R6.2 TP2.1 | length 575.2
  Top Layer w15: TP2.1@3950,1895 4035.63,1980.63 R6.2@4035.63,2045 4035.63,2384.37 P4.1@4000,2420
NetP8_1: P8.1 R19.2 R21.1 | length 577
  Top Layer w20: R19.2@385,3095 385,2957.31 R21.1@491.37,2850.94 ; R21.1@491.37,2845 R21.1@491.37,2850.94 ; P8.1@725,2970 610.43,2970 R21.1@491.37,2850.94
NetP9_1: P9.1 R20.2 R23.1 | length 620.8
  Top Layer w20: R20.2@1175,3095 1175,2942.31 R23.1@1266.37,2850.94 ; R23.1@1266.37,2845 R23.1@1266.37,2850.94 ; P9.1@1550,2970 1391.37,2970 1286.06,2864.69 1280.12,2864.69 R23.1@1266.37,2850.94
NetP10_1: P10.1 R30.2 R31.1 TP6.1 | length 935.7
  Top Layer w20: TP6.1@1595,3215 1595,3117 1695,3017 1847,3017 R30.2@1925,3095 1925,2873.11 1950,2848.11 P10.1@1950,2845 R31.1@1776.37,2845
NetP12_2: P12.2 U4.2 U4.6 | length 656.7
  Top Layer w15: P12.2@3400,1795 3494.71,1889.71 3494.71,2057.82 3581.89,2145 U4.6@3607.48,2145 3633.07,2145 3683.07,2095 U4.2@3792.52,2095
NetR6_1: R6.1 U10.8 | length 124.4
  Top Layer w10: R6.1@4114.37,2045 U10.8@4238.75,2045
SEDE_0.5V: C25.1 TP4.1 U5.2 U11.1 U11.2 | length 732.6
  Top Layer w20: TP4.1@3044,2551 3128.72,2551 3158.6,2580.88 ; U5.2@3075,2212.52 3075,2238.11 3135.93,2299.04 3159.04,2299.04 v1(3160,2300) ; v1(3210,2350) 3230.63,2370.63 C25.1@3230.63,2420 3230.63,2424.92 3158.6,2496.95 3158.6,2580.88 ; U11.1@3240,2630 U11.2@3240,2592.6 ; U11.2@3245.73,2592.6 U11.2@3240,2592.6 ; 3158.6,2580.88 3170.31,2592.6 U11.2@3240,2592.6
  Int1 (GND) w10: v1(3160,2300) v1(3210,2350)
SEDE_INPUT: P12.1 R22.1 TP3.1 | length 378.7
  Top Layer w15: TP3.1@3160,1800 3295,1800 P12.1@3300,1795 3388.43,1883.43 R22.1@3388.43,1995
V_SIN_IN_N: J9.1 J11.1 R28.2 | length 2575.4
  Top Layer w10: R28.2@2595,1763.39 2595,1824.09 ; J9.1@2595,1870 2595,1824.09 ; J11.1@5000,1670 2749.09,1670 2595,1824.09
V_SIN_IN_P: C17.1 J2.1 J12.3 R17.1 TP1.1 | length 3366.2
  Top Layer w10: J12.3@2595,2370 2604.91,2379.91 2604.91,2409.3 2915.75,2720.14 4724.86,2720.14 TP1.1@5000,2445 J2.1@5000,2120 ; C17.1@4661.42,2095 C17.1@4674.8,2081.61 ; R17.1@4775,2081.61 R17.1@4784.84,2081.61
  Top Layer w15: C17.1@4674.8,2081.61 R17.1@4775,2081.61 ; R17.1@4784.84,2081.61 4823.23,2120 J2.1@5000,2120
VDD_2.5V: C2.1 C4.1 C11.2 C13.2 C15.2 J3.1 J13.1 U7.1 U7.3 U8.1 U8.3 U9.1 U9.3 | length 5025.2
  Top Layer w20: C13.2@225,3472.56 C13.2@229.92,3472.56 ; U7.3@367.6,3442 367.6,3458 353.04,3472.56 C13.2@229.92,3472.56 ; U7.1@442.4,3442 442.4,3582.74 425,3600.14 C4.1@425,3733.58 ; J13.1@770,2370 800,2400 800,3667.64 ; J3.1@793,3987.5 848.94,3931.56 848.94,3903.25 1102.81,3649.39 1468.25,3649.39 1645.08,3472.56 C15.2@1650,3472.56 1773.04,3472.56 1787.6,3458 U9.3@1787.6,3442 1787.6,3426 1799,3414.6 1799,3409.37 1808.37,3400 1841.63,3400 1851,3409.37 1851,3414.6 1862.4,3426 U9.1@1862.4,3442 ; U8.1@1237.4,3442 1237.4,3426 1226,3414.6 1226,3409.37 1216.63,3400 1183.37,3400 1174,3409.37 1174,3414.6 1162.6,3426 U8.3@1162.6,3442 1162.6,3458 1148.04,3472.56 C11.2@1000,3472.56 995.08,3472.56 800,3667.64 ; C13.2@229.92,3472.56 260,3502.64 C2.1@260,3730.63 261.48,3732.11 423.52,3732.11 C4.1@425,3733.58 ; C4.1@425,3733.58 433.7,3724.88 453.75,3724.88 454.27,3724.36 752.64,3724.36 764.36,3736.08 764.36,3901.86 800,3937.5 800,3667.64
pads on no net: J1.2 J1.3 J1.4 J1.5 J2.2 J2.3 J2.4 J2.5 J3.2 J3.3 J3.4 J3.5 J4.2 J4.3 J4.4 J4.5 J5.2 J5.3 J5.4 J5.5 J6.2 J6.3 J6.4 J6.5 J7.2 J7.3 J7.4 J7.5 J8.2 J8.3 J8.4 J8.5 J11.2 J11.3 J11.4 J11.5 MP1. MP2. MP3. MP4. U1.4 U2.2 U2.3 U2.5 U2.6 U2.8 U3.4 U4.1 U4.5 U4.8 U5.7 U7.4 U8.4 U9.4 U11.4
copper on no net:
  other v1: 2860,2620

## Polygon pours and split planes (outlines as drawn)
+5 on Int2 (PWR) "+5_L03_P003" (solid, pour order 3): 5175,4445 2250,4445 2250,1145 2225,1120 30,1120 30,20 5175,20
VDD_2.5V on Int2 (PWR) "VDD_2.5V_L03_P000" (solid, pour order 0): 72.38,4422.18 72.38,2720 2150,2720 2150,4419.81
-5 on Bottom Layer "-5_L04_P004" (solid, pour order 4): 5180,4450 2255,4450 2250,4445 2250,1120 30,1120 30,40 5180,40
DGND on Int1 (GND) "DGND_L02_P007" (solid, pour order 7): 5200,4450 2230,4450 2230,1120 500,1120 500,2445 0,2445 0,0 5200,0
AGND on Int1 (GND) "AGND_L02_P005" (solid, pour order 5): 0,4470 0,2470 525,2470 525,1170 2225,1170 2225,4470

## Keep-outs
Keep-Out Layer:
  the board outline again, w24

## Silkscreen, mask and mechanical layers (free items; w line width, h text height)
Top Overlay:
  lines w1: 550,1370 2045,1370 2045,2670 550,2670 550,1370
  text "+2.5V" at 530,3573 h100
  text "CHIP_GND" at 1069,3568 h100
  text "+5V" at 3580,3490 h100
  text "D_GND" at 2265,3485 h100
  text "-5V" at 2965,3485 h100
  text "D_GND" at 4225,3485 h100
  text "DGND_TP" at 3202,3122 h40
  text "VCM" at 1548,3096 h30
  text "Single / Point / Connection" at 2285,3030 h40
  text "DGND_TP" at 4722,2954 h40
  text "500k" at 4157,2909 h40
  text "1M" at 4415,2909 h40
  text "AGND" at 68,2886 h30
  text "SEDE_VOCM_0.5V" at 2775,2880 h60
  text "CUTOFF_Choice" at 4125,2815 h40
  text "DVDD_1V" at 145,2650 h60
  text "AVDD_ESD" at 945,2645 h60
  text "VCM_0.5V" at 1665,2640 h60
  text "Buffer" at 3840,2585 h40
  text "SIN_IN_P" at 2180,2350 h40
  text "Filter" at 4450,2265 h40
  text "768.747mil" at 1444,2049 h30
  text "SEDE" at 3340,1875 h40
  text "768.748mil" at 1449,1842 h30
  text "SIN_IN_N" at 2180,1830 h40
  text "MUX" at 258.38,1650 h40
  text "DGND_TP" at 3568,1296 h40
  text "ChengmingLi/MingjieMa / 9-Bit ADC-MotherBoard" at 2954,769 h80
  text "10/20/2024 / No.1" at 2954,457 h80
